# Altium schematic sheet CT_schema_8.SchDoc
size 254 x 194 mm
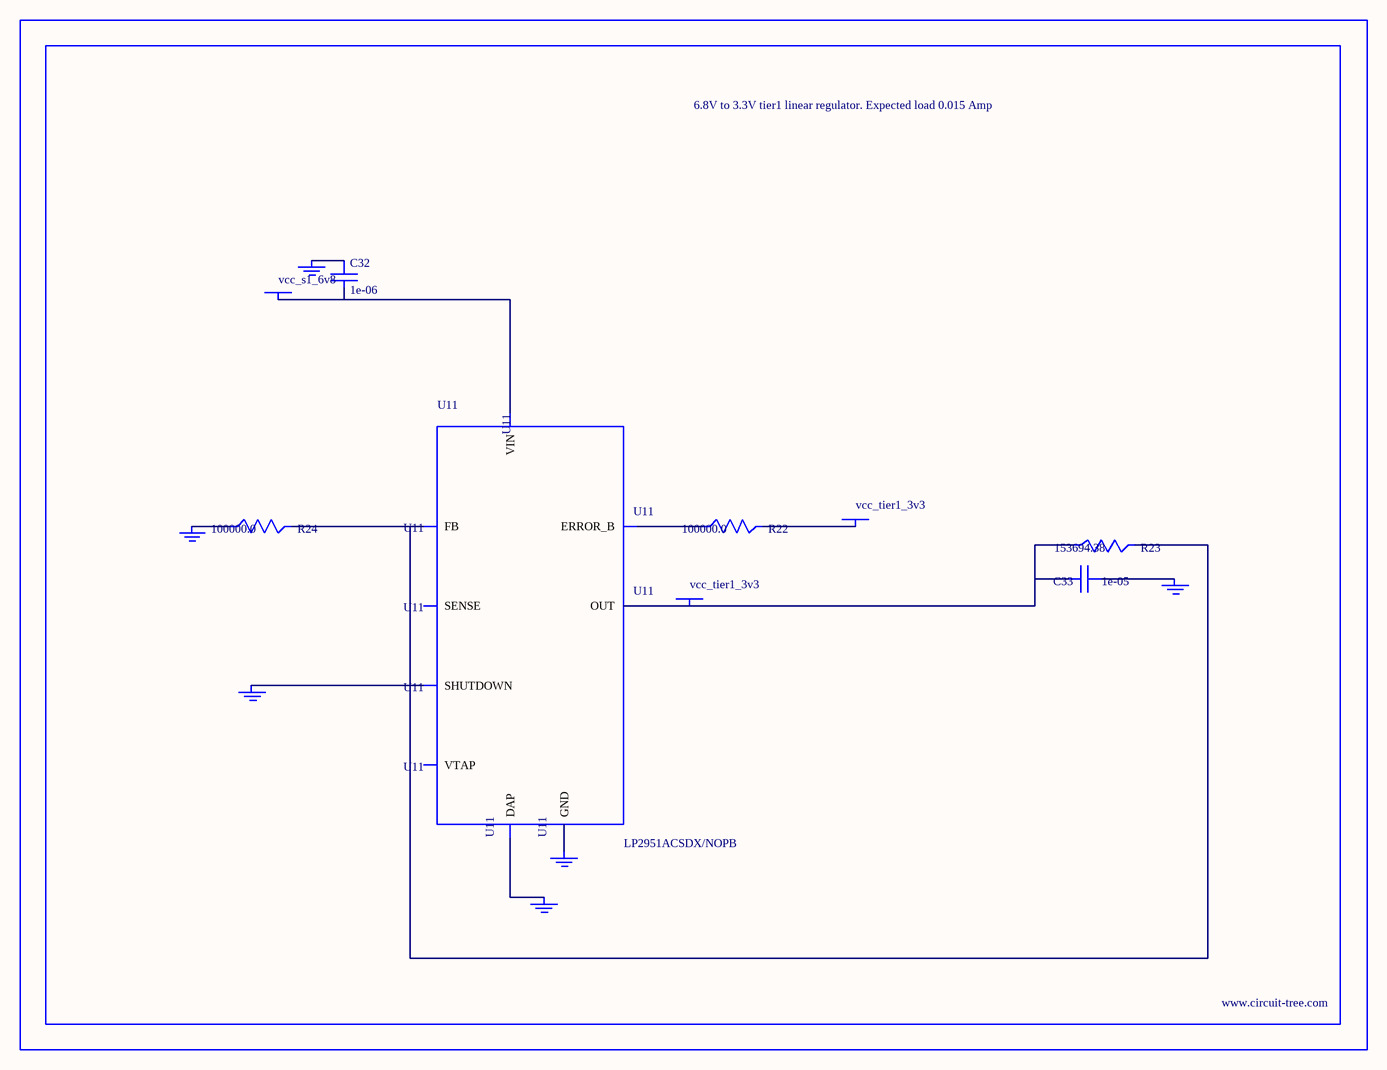
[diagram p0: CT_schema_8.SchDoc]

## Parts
BORDER7  (no value)
C32  1e-06  [C0603]
C33  1e-05  [C1210]
GND_INSTANCE_7_0  (no value)
GND_INSTANCE_7_1  (no value)
GND_INSTANCE_7_2  (no value)
GND_INSTANCE_7_3  (no value)
GND_INSTANCE_7_4  (no value)
GND_INSTANCE_7_5  (no value)
POWER_INSTANCE_7_0  vcc_tier1_3v3
POWER_INSTANCE_7_1  vcc_s1_6v8
POWER_INSTANCE_7_2  vcc_tier1_3v3
R22  100000.0  [R0603]
R23  153694.38  [R0603]
R24  100000.0  [R0603]
U11  LP2951ACSDX/NOPB  [WSON-8]

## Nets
NetC32_1: C32.1 GND_INSTANCE_7_3.0(GND)
NetC32_2: C32.2 POWER_INSTANCE_7_1.0(PWR) U11.8(VIN)
NetC33_1: C33.1 GND_INSTANCE_7_0.0(GND)
NetC33_2: C33.2 POWER_INSTANCE_7_2.0(PWR) R23.1 U11.1(OUT)
NetGND_INSTANCE_7_1_0: GND_INSTANCE_7_1.0(GND) U11.3(SHUTDOWN)
NetGND_INSTANCE_7_2_0: GND_INSTANCE_7_2.0(GND) R24.1
NetGND_INSTANCE_7_4_0: GND_INSTANCE_7_4.0(GND) U11.PAD(DAP)
NetGND_INSTANCE_7_5_0: GND_INSTANCE_7_5.0(GND) U11.4(GND)
NetPOWER_INSTANCE_7_0_0: POWER_INSTANCE_7_0.0(PWR) R22.2
NetR22_1: R22.1 U11.5(ERROR_B)
NetR23_2: R23.2 R24.2 U11.7(FB)

Not connected (* = marked no-connect by the designer): U11 2(SENSE) 6(VTAP)

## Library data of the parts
BORDER7 = BORDER_PAGE7
C32 = C0603C105K3RACTU
C33 = GRM32DR61E106MA12L
GND_INSTANCE_7_0-GND_INSTANCE_7_5 = GND
POWER_INSTANCE_7_0-POWER_INSTANCE_7_2 = PWR
R22 R24 = RC0603JR-07100KL
R23 = R23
